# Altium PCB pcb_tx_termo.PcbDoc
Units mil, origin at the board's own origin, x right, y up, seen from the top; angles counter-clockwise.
Board outline 2385 x 1585 mil, 2 copper layers (Top Layer, Bottom Layer); 31 components, 31 nets, 126 pads, 0 vias.
Unrouted connection lines stored in the file: 4.
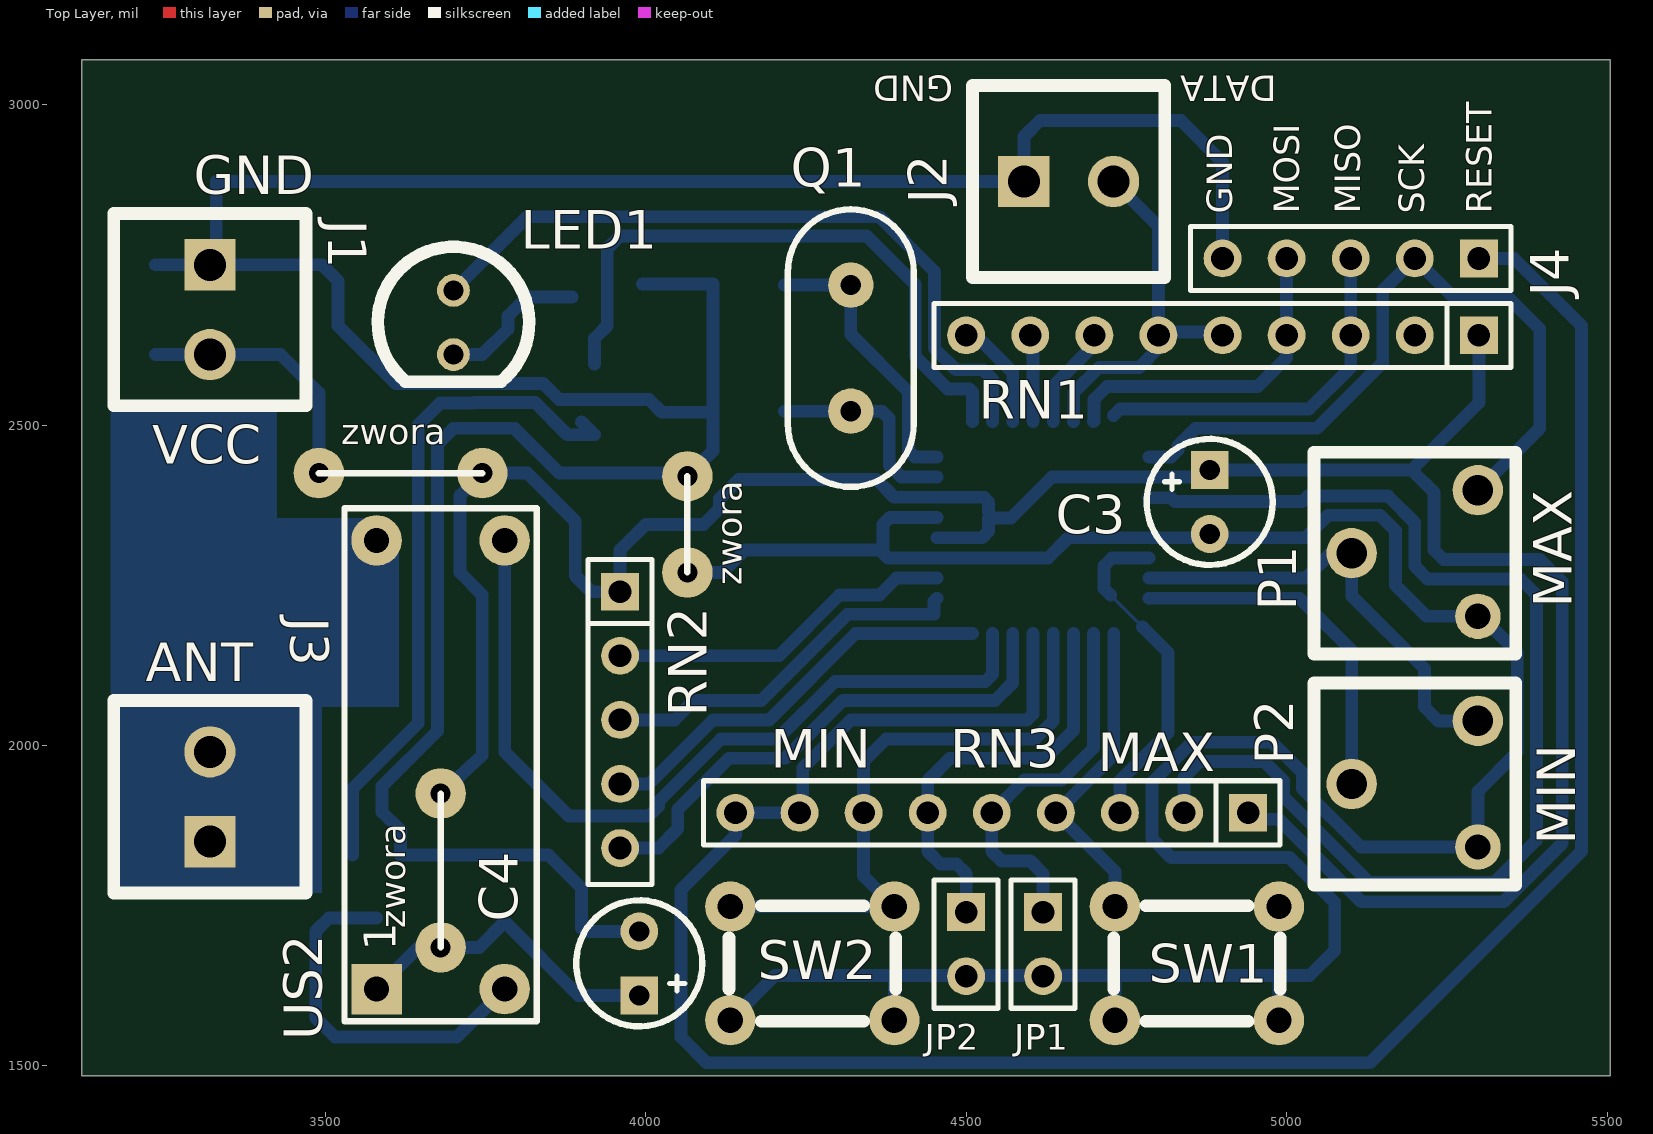
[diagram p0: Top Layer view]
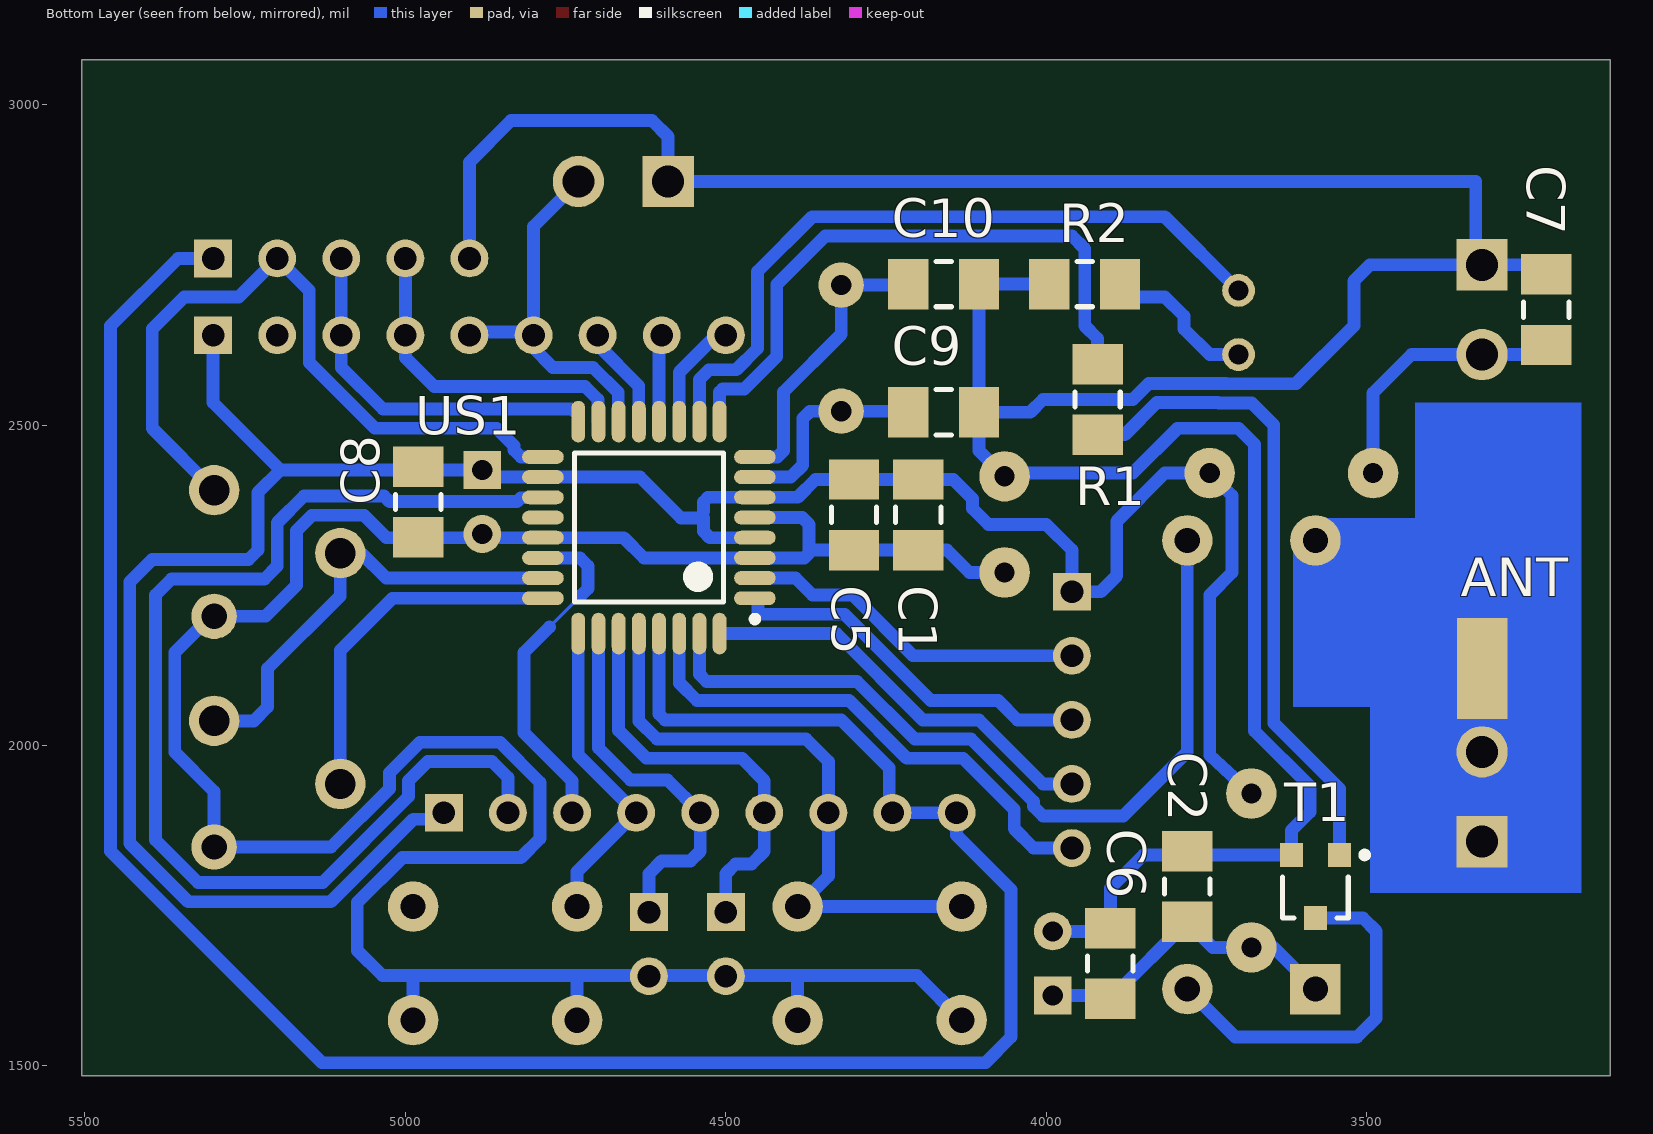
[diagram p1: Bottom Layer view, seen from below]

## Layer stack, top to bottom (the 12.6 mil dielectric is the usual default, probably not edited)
Top Layer: signal copper 1.4
Dielectric: dielectric 12.6, FR-4, Dk 4.8
Bottom Layer: signal copper 1.4

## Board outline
3120,1485 5505,1485 5505,3070 3120,3070

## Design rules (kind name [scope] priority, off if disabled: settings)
Clearance [All] p1: gap=10
PolygonConnect [All] p1: connectstyle=Relief reliefconductorwidth=10 reliefentries=4 polygonreliefangle="90 Angle"
RoutingVias [All] p1: holewidth=28 width=50 viastyle="Through Hole" minholewidth=28 minwidth=50 maxholewidth=28 maxwidth=50
SilkscreenOverComponentPads [All] p1: minsilkscreentomaskgap=10
SolderMaskExpansion [All] p1: expansion=4
Width [All] p1: maxlimit=100 minlimit=5 preferedwidth=20
27 further rules are at their usual default settings.

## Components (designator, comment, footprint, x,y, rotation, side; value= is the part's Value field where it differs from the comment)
ANT "Pad" "Pad SMD 2x4mm" 3320,2120 r270 bottom
C1 "100n" MELF-1206 4200,2360 r90 bottom
C2 "100n" MELF-1206 3780,1780 r270 bottom
C3 "100u" "2,5/5mm elektrolit" 4880,2380 r270 top
C4 "100u" "2,5/5mm elektrolit" 3990,1660 r90 top
C5 "10n" MELF-1206 4300,2360 r90 bottom
C6 "10n" MELF-1206 3900,1660 r270 bottom
C7 "10n" MELF-1206 3220,2680 r270 bottom
C8 "10n" MELF-1206 4980,2380 r90 bottom
C9 "22p" MELF-1206 4160,2520 r180 bottom
C10 "22p" MELF-1206 4160,2720 r180 bottom
J1 "ARK2" "ARK2 3,5mm" 3320,2680 r270 top
J2 "ARK2" "ARK2 3,5mm" 4660,2880 r0 top
J3 "ARK2" "ARK2 3,5mm" 3320,1920 r90 top
J4 "Goldpin 5pin" HDR1X5 5300,2760 r180 top
JP1 "zworka" HDR1X2 4620,1740 r270 top
JP2 "zworka" HDR1X2 4500,1740 r270 top
LED1 "5mm green" "LED 5mm" 3700,2660 r90 top
P1 "10k" "pot mont poziom" 5200,2300 r90 top
P2 "10k" "pot mont poziom" 5200,1940 r90 top
Q1 "4MHz" "kwarc 5mm" 4320,2620 r90 top
R1 "10k" MELF-1206 3920,2540 r90 bottom
R2 "470" MELF-1206 3940,2720 r180 bottom
RN1 "8x10k" SIL9 5300,2640 r180 top
RN2 "4x10k" SIL5 3960,2240 r270 top
RN3 "8x10k" SIL9 4940,1895 r180 top
SW1 "6x6" "tact switch 6x6" 4860,1660 r0 top
SW2 "6x6" "tact switch 6x6" 4260,1660 r0 top
T1 "BC846" 318-08 3580,1780 r0 bottom
US1 "ATmega8L" 32A_N 4620,2340 r0 bottom
US2 "RT4_Tx" RT4_Tx 3580,1620 r90 top

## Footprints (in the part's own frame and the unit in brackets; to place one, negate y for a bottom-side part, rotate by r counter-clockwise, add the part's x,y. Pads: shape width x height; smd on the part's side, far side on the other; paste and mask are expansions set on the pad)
"2,5/5mm elektrolit" [mm]
  rect 1.5x1.5 hole 0.8: 1(-1.27,0)
  round 1.5 hole 0.8: 2(1.27,0)
  silkscreen extent -2.5,-2.5 2.5,2.5
32A_N [mm] "Thin QFP, 32-Leads, Body 7x7mm, Pitch 0.8mm, IPC Medium Density"
  oval 1.65x0.55 smd: 1(-4.2,2.8) 2(-4.2,2) 3(-4.2,1.2) 4(-4.2,0.4) 5(-4.2,-0.4) 6(-4.2,-1.2) 7(-4.2,-2) 8(-4.2,-2.8) 17(4.2,-2.8) 18(4.2,-2) 19(4.2,-1.2) 20(4.2,-0.4) 21(4.2,0.4) 22(4.2,1.2) 23(4.2,2) 24(4.2,2.8)
  oval 0.55x1.65 smd: 9(-2.8,-4.2) 10(-2,-4.2) 11(-1.2,-4.2) 12(-0.4,-4.2) 13(0.4,-4.2) 14(1.2,-4.2) 15(2,-4.2) 16(2.8,-4.2) 25(2.8,4.2) 26(2,4.2) 27(1.2,4.2) 28(0.4,4.2) 29(-0.4,4.2) 30(-1.2,4.2) 31(-2,4.2) 32(-2.8,4.2)
  silkscreen extent -4.32,-2.95 2.95,3.75, body extent -3.5,-3.5 3.5,3.5, height 1.2
318-08 [mm] "SOT-23; 3 Leads; Body 3.0 x 2.6 mm, inc. leads (LxW max)"
  rect 0.9x0.95 smd: 1(-0.95,-1.25) 2(0.95,-1.25) 3(0,1.25)
  silkscreen extent -2.07,-1.37 1.3,1.25
"ARK2 3,5mm" [mil]
  rect 80x80 hole 50: 1(-70,0)
  round 80 hole 50: 2(70,0)
  silkscreen extent -150,-150 150,150, body extent -150,-140 150,160, height 400
HDR1X2 [mm] "Connector; Header; 2 Position"
  rect 1.5x1.5 hole 0.9: 1(0,0)
  round 1.5 hole 0.9: 2(2.54,0)
  silkscreen extent -1.27,-1.27 3.81,1.27
HDR1X5 [mm] "Connector; Header; 5 Position"
  rect 1.5x1.5 hole 0.9: 1(0,0)
  round 1.5 hole 0.9: 2(2.54,0) 3(5.08,0) 4(7.62,0) 5(10.16,0)
  silkscreen extent -1.27,-1.27 11.43,1.27
"kwarc 5mm" [mm]
  round 1.8 hole 0.8: 1(-2.5,0) 2(2.5,0)
  silkscreen extent -5.5,-2.5 5.5,2.5
"LED 5mm" [mm]
  round 1.3 hole 0.8: A(1.27,0) K(-1.27,0)
  silkscreen extent -2.35,-3 3,3
MELF-1206 [mm] "Metal Electrode Face (MELF) Resistor; Body 3.2 x 1.8 mm (LxDia)"
  rect 1.6x2 smd: 1(-1.4,0) 2(1.4,0)
  silkscreen extent -0.3,-0.9 0.3,0.9, body extent -2.3,-1.1 2.3,1.1, height 1.85
"Pad SMD 2x4mm" [mm]
  rect 4x2 smd: 1(0,0)
"pot mont poziom" [mm]
  round 1.8 hole 1: a(-2.5,-2.5)
  round 2 hole 1.2: b(2.5,-2.5) c(0,2.5)
  silkscreen extent -4,-4 4,4
RT4_Tx [mm]
  rect 2x2 hole 1: 1(0,0)
  round 2 hole 1: 2(0,-5.08) 3(17.78,-5.08) 4(17.78,0)
  silkscreen extent -1.27,-6.35 19.05,1.27, body extent -1.1,-6.18 18.88,1.1, height 4
SIL5 [mm] "Connector; Header; 9 Position"
  rect 1.5x1.5 hole 0.9: 1(0,0)
  round 1.5 hole 0.9: 2(2.54,0) 3(5.08,0) 4(7.62,0) 5(10.16,0)
  silkscreen extent -1.27,-1.27 11.6,1.27
SIL9 [mm] "Connector; Header; 9 Position"
  rect 1.5x1.5 hole 0.9: 1(0,0)
  round 1.5 hole 0.9: 2(2.54,0) 3(5.08,0) 4(7.62,0) 5(10.16,0) 6(12.7,0) 7(15.24,0) 8(17.78,0) 9(20.32,0)
  silkscreen extent -1.27,-1.27 21.59,1.27
"tact switch 6x6" [mm]
  round 2 hole 1: 1(3.25,2.25) 2(3.25,-2.25) 3(-3.25,2.25) 4(-3.25,-2.25)
  silkscreen extent -3.3,-2.29 3.3,2.29

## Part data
C1 C2 C5 C6 C7 C8 C9 C10: library part kondensator
C3 C4: library part "kond biegunowy", "Polarized Capacitor"
J4: library part "Header 5", "Header, 5-Pin"
JP1 JP2: library part "Header 2", "Header, 2-Pin"
LED1: library part LED
P1 P2: library part "pot mont"
Q1: library part kwarc
R1 R2: library part rezystor
RN1 RN3: library part "drab rez x 8", "Header, 9-Pin"
RN2: library part "drab rez x 4", "drab rez x 4"
SW1 SW2: library part switch
T1: library part BC846ALT1, "General Purpose Transistor NPN Silicon"
US1: library part ATmega8L-8AI, "8-Bit AVR Microcontroller with 8K Bytes of In-System Programmable Flash Memory"

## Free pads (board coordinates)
  round 78.74 hole 31.5: 0(3490,2425) 0(3680,1685) 0(3680,1925) 1(3745,2425) 2(4065,2420) 3(4065,2270)

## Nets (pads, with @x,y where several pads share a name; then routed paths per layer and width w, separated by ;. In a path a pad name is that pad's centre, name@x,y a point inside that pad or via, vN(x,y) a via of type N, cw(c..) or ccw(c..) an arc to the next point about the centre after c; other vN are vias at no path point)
1WIRE: J2.2 RN1.5 RN1.6 US1.14 | length 595.4
  Bottom Layer w20: US1.14 4667.91,2506.02 4667.91,2550.71 4707.21,2590 4770,2590 4800,2620 RN1.6 RN1.6@4800,2645 ; J2.2 4800,2810 RN1.6@4800,2645 ; RN1.5@4900,2645 RN1.6@4800,2645
ADC6: RN3.2 US1.19 | length 1832.6
  Bottom Layer w20: US1.19 4786.02,2386.57 4819.78,2386.57 4825.88,2380.47 5024.5,2380.47 5033.4,2389.37 5158.06,2389.37 5200,2347.43 5200,2280 5220,2260 5365,2260 5390,2235 5390,1852.57 5323.57,1786.14 5129.04,1786.14 4995,1920.19 4995,1945 4965,1975 4865,1975 4840,1950 RN3.2
ADC7: RN3.3 US1.22 | length 533.1
  Bottom Layer w5: 4725,2235 4775,2185
  Bottom Layer w20: 4725,2235 4715,2245 4715,2280 4727.76,2292.76 US1.22 ; RN3.3 4740,1945 4815,2020 4815,2145 4775,2185
DATA: US1.31 US2.3 | length 1292.1
  Bottom Layer w20: US2.3 3780,1990 3880,1890 4005,1890 4020,1905 4020,1912.43 4117.57,2010 4205.15,2010 4295.15,2100 4530,2100 4541.26,2111.26 US1.31
GND: C1.1 C2.1 C3.2 C4.2 C5.1 C6.1 C7.1 C8.1 C9.2 C10.2 J1.1 J2.1 J4.5 JP1.2 JP2.2 P1.a P2.a pad.2 pad.3 R2.1 SW1.2 SW1.4 SW2.2 SW2.4 T1.2 US1.3 US1.5 US1.21 | length 9191.2
  Bottom Layer w20: C7.1@3234.88,2750 J1.1 ; 3425,2750 3410,2750 ; C4.2 3905.12,1710 C6.1 3900,1777.57 3848.36,1829.21 T1.2 3617.4,1867.6 3588.71,1896.29 3588.71,1936.29 3675,2022.57 3675,2470 3700,2495 3795,2495 3865,2425 4043.23,2425 pad.2@4051.61,2433.39 ; R2.1 C10.2 C9.2 ; pad.3 4120,2270 4154.88,2304.88 C1.1 C5.1 4365.63,2304.88 ; pad.2 4104.88,2459.88 C9.2 ; SW2.4 4201.57,1640.94 4620,1640.94 5035.94,1640.94 5075,1680 5075,1755 5005,1825 4820,1825 4790,1855 4790,1942.43 4852.57,2005 4977.43,2005 5025,1957.43 5025,1932.61 5116.04,1841.57 P2.a 5298.43,1928.43 5360,1990 5360,2145 P1.a@5300.93,2204.07 ; SW2.2 4387.95,1637.99 ; US1.5 4380.75,2355.75 4370,2345 4370,2300.51 4377.76,2292.76 US1.3 4627.76,2292.76 4659.25,2324.25 US1.21 5029.25,2324.25 5064.37,2359.37 5145.63,2359.37 5170,2335 5170,2250 5218.43,2201.57 P1.a ; SW1.4 4732.05,1637.99 ; J4.5 4900,2910 4835,2975 4615,2975 4590,2950 J2.1 3330,2880 3330,2750 3410,2750 ; SW1.2 4987.95,1638.9 ; 3410,2750 3495,2750 3520,2725 3520,2655 3610.59,2564.41 3718.88,2564.41 3719.47,2565 3840,2565 3865,2540 4005,2540 4025,2520 C9.2
JP_MAX: JP1.1 RN3.5 US1.26 | length 600.7
  Bottom Layer w20: RN3.5@4545,1890 RN3.5 ; JP1.1 4620,1800 4600,1820 4555,1820 4540,1835 RN3.5 ; US1.26 4698.74,1996.17 4648.79,1946.21 4591.21,1946.21 RN3.5
JP_MIN: JP2.1 RN3.6 US1.27 | length 655.4
  Bottom Layer w20: JP2.1 4500,1800 4485,1815 4460,1815 4440,1835 RN3.6 4440,1945 4475,1980 4623.79,1980 4667.24,2023.46 US1.27
LED: LED1.A US1.10 | length 1130.3
  Bottom Layer w20: LED1.A 3815,2825 4365,2825 4450.47,2739.53 4450.47,2619.49 4483.67,2586.29 4526.29,2586.29 4541.26,2571.31 US1.10
MISO: J4.3 RN1.3 US1.16 | length 571.1
  Bottom Layer w20: US1.16@4730,2515 4740,2525 5035,2525 5100,2590 RN1.3 J4.3
MOSI: J4.4 RN1.4 US1.15 | length 517.3
  Bottom Layer w20: US1.15 4699.41,2506.02 4699.41,2539.78 4719.63,2560 4955,2560 5000,2605 RN1.4 J4.4
NetANT_1: ANT.1 J3.1 J3.2 US2.4 | length 755.4
  Bottom Layer w70: J3.1@3320,1810 3320,2295 3345,2320 3480,2320 US2.4
NetLED1_K: LED1.K R2.2 | length 233.9
  Bottom Layer w20: LED1.K 3745,2610 3785,2650 3785,2670 3815,2700 R2.2@3884.88,2700
NetR1_1: R1.1 T1.1 | length 1051.9
  Bottom Layer w20: T1.1 3542.6,1932.6 3645,2035 3645,2500 3679.41,2534.41 3731.31,2534.41 3731.9,2535 3827.57,2535 3877.69,2484.88 R1.1 R1.1@3899.88,2505
NetT1_3: T1.3 US2.2 | length 577.1
  Bottom Layer w20: T1.3 3505.79,1730.79 3485,1710 3485,1575 3515,1545 3705,1545 US2.2
PB0: RN1.8 US1.12 | length 134.6
  Bottom Layer w20: US1.12 RN1.8@4604.25,2640
PB1: RN1.7 US1.13 | length 161.3
  Bottom Layer w20: US1.13 4635.75,2560.97 4700,2625.22 RN1.7
PD0: RN2.5 US1.30 | length 814
  Bottom Layer w20: RN2.5 4020,1840 4050,1870 4050,1900 4130,1980 4217.57,1980 4307.57,2070 4545,2070 4572.76,2097.76 US1.30
PD2: RN2.4 US1.32 | length 647
  Bottom Layer w20: RN2.4 4005.15,1940 4105.15,2040 4192.72,2040 4327.37,2174.65 US1.32
PD3: RN2.3 US1.1 | length 585.2
  Bottom Layer w20: RN2.3 4045,2040 4075,2070 4180.29,2070 4314.94,2204.65 4450,2204.65 4450,2225.12 US1.1
PD4: RN2.2 US1.2 | length 544.9
  Bottom Layer w20: RN2.2 4207.87,2140 4302.51,2234.65 4364.65,2234.65 4391.26,2261.26 US1.2
PD7: RN1.9 US1.11 | length 179.8
  Bottom Layer w20: RN1.9@4500,2655 4572.76,2582.24 US1.11
POT_MAX: P1.c P2.b US1.23 | length 709.8
  Bottom Layer w20: US1.23 5030,2261.26 5068.74,2300 P1.c@5081.57,2300 ; P1.c 5101.57,2233.43 5215,2120 5215,2060 5236.57,2038.43 P2.b ; P2.b@5278.43,2038.43 P2.b@5278.43,2056.57
POT_MIN: P2.c US1.24 | length 582.2
  Bottom Layer w20: US1.24 5020.24,2229.76 5100,2150 ; P2.c@5081.57,1940 P2.c@5100,1958.43 ; P2.c 5101.57,2148.43
RST: J4.1 RN3.8 RN3.9 US1.29 | length 3651.5
  Bottom Layer w20: RN3.8 RN3.9 4140,1860 4055,1775 4055,1706.31 4055,1587.57 4055,1545 4095,1505 5130,1505 5460,1835 5460,2655 5355,2760 J4.1 ; RN3.8@4245,1900 4245,1965 4320,2040 4595,2040 4604.25,2049.25 US1.29
SCK: J4.2 P1.b US1.17 | length 1145
  Bottom Layer w20: US1.17 4819.76,2450.24 4830.47,2460.94 4830.47,2467.81 4857.66,2495 5047.43,2495 5150,2597.57 5150,2710 J4.2 5260,2700 5345,2700 5395,2650 5395,2495 P1.b
SW_MAX: RN3.4 SW1.1 SW1.3 US1.25 | length 501.6
  Bottom Layer w20: US1.25 4730.24,1985.24 RN3.4 4732.05,1802.95 SW1.3
SW_MIN: RN3.7 SW2.1 SW2.3 US1.28 | length 960.5
  Bottom Layer w20: SW2.3 SW2.1 4340,1796.54 RN3.7 4340,1975 4375,2010 4607.43,2010 4635.75,2038.32 US1.28
TX_ON: R1.2 US1.9 | length 979.1
  Bottom Layer w20: R1.2 3920,2635 3940,2655 3940,2775 3960,2795 4345,2795 4420.47,2719.53 4420.47,2607.06 4471.24,2556.29 4505,2556.29 4509.76,2551.52 US1.9
VCC: C1.2 C2.2 C3.1 C4.1 C5.2 C6.2 C7.2 C8.2 J1.2 pad.0 pad.1 RN1.1 RN2.1 RN3.1 US1.4 US1.6 US1.18 US2.1 | length 4949.8
  Bottom Layer w20: C7.2@3234.88,2610 J1.2 ; J1.2@3340,2610 3430,2610 3490,2550 pad.0@3490,2430 ; US2.1 3645,1685 3740.12,1685 C2.2 C6.2@3894.88,1610 ; pad.0@3680,1925 3745,1985 3745,2235 3710,2270 3710,2390 pad.1 ; pad.1@3730,2425 pad.1 ; pad.1@3750,2425 pad.1 ; pad.1@3760,2415 pad.1 ; C6.2@3884.88,1620 C6.2@3894.88,1610 ; C4.1 C6.2@3894.88,1610 ; US1.4 4525,2324.25 4535,2334.25 4535,2355 4570,2355 4633.74,2418.74 US1.18 4868.74,2418.74 C3.1 5195,2430 ; 4535,2365 4535,2380 4527.76,2387.24 US1.6 4387.76,2387.24 4359.88,2415.12 C5.2 C1.2 4145.12,2415.12 4115,2385 4115,2370 4090,2345 4000,2345 3960,2305 RN2.1 3915,2240 3890,2265 3890,2350 3815,2425 pad.1 ; RN3.1@4945,1885 4987.76,1885 5116.62,1756.14 5338.72,1756.14 5430,1847.43 5430,2255 5395,2290 5245,2290 5230,2305 5230,2395 5195,2430 ; RN1.1 5300,2535 5195,2430
XTAL1: C9.1 Q1.1 US1.7 | length 323.1
  Bottom Layer w20: C9.1@4216.69,2521.57 Q1.1 4368.43,2521.57 4380,2510 4380,2437.43 4398.69,2418.74 US1.7
XTAL2: C10.1 Q1.2 US1.8 | length 449.9
  Bottom Layer w20: C10.1@4216.69,2718.43 Q1.2 ; Q1.2@4318.43,2720 Q1.2 ; US1.8 4419.76,2450.24 4410,2460 4410,2551.57 4320,2641.57 Q1.2
pads on no net: RN1.2 US1.20

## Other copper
Bottom Layer:
  rectangle net NetANT_1: 3165,1770 3495,2355
  rectangle net NetANT_1: 3165,2340 3425,2535
  rectangle net NetANT_1: 3430,2060 3615,2320

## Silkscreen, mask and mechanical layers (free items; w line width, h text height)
Top Overlay:
  lines w10: 3490,2425 3745,2425 ; 3680,1685 3680,1925 ; 4065,2270 4065,2420
  text "GND" at 4480,3045 h40 r180
  text "DATA" at 4985,3045 h40 r180
  text "GND" at 3295,2860 h60
  text "GND" at 4915,2830 h40 r90
  text "MOSI" at 5020,2830 h40 r90
  text "MISO" at 5115,2830 h40 r90
  text "SCK" at 5215,2830 h40 r90
  text "RESET" at 5320,2830 h40 r90
  text "zwora" at 3525,2470 h40
  text "VCC" at 3230,2440 h60
  text "zwora" at 4150,2250 h40 r90
  text "MAX" at 5445,2215 h60 r90
  text "ANT" at 3220,2100 h60
  text "MIN" at 4195,1965 h60
  text "MAX" at 4705,1960 h60
  text "MIN" at 5450,1845 h60 r90
  text "zwora" at 3625,1715 h40 r90
Mechanical 1:
  the board outline again, w10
